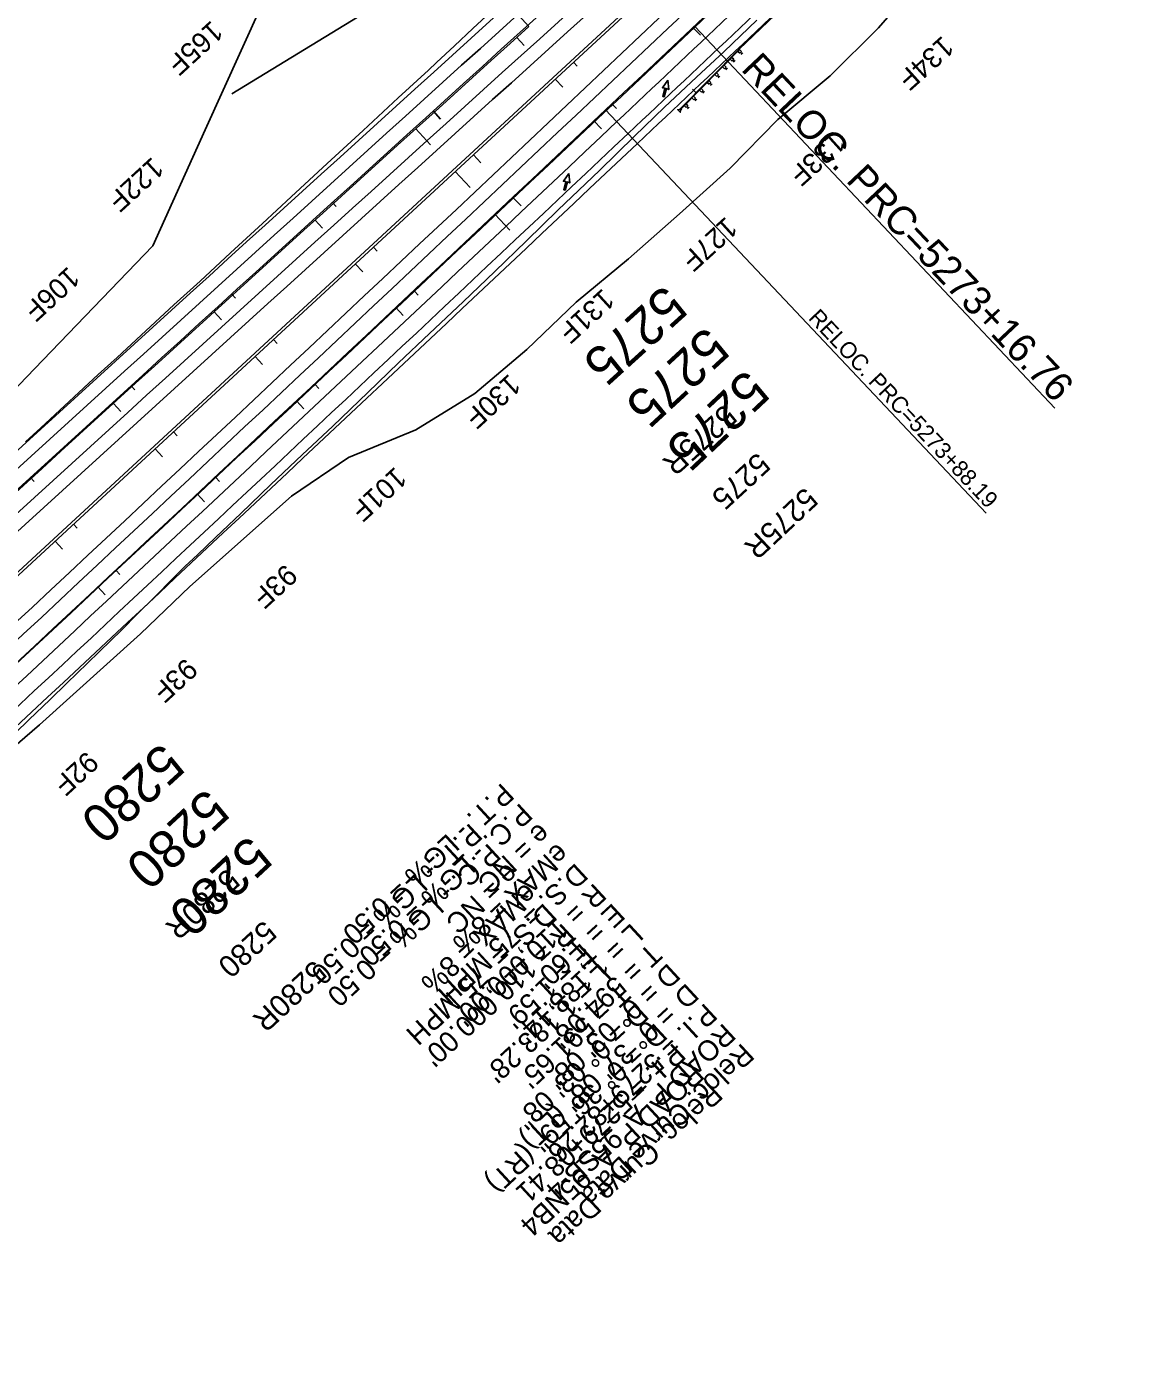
# Model space of a CAD drawing. Extents: x 2160876 to 2175990, y 601436 to 618246.
# Drawn here: x 2164326 to 2165140, y 605855 to 606830 of the extents above; entities that cross this region are included whole.
import ezdxf

# ---------------------------------------------------------------- set-up
doc = ezdxf.new("R2010")
doc.units = 0
for name, color, linetype in [('BNDY-ADJ', 7, 'Continuous'), ('BNDY-ADJ-TXT', 7, 'Continuous'), ('EX-UTIL-ELEC-TXT', 7, 'Continuous'), ('RD_DTM_Major2', 7, 'Continuous'), ('RD_EX_BldgApp_Sign', 7, 'Continuous'), ('RD_EX_BldgApp_Steps', 7, 'Continuous'), ('RD_EX_DV_Prop_Easement Lines', 7, 'Continuous'), ('RD_EX_DV_Prop_Property Lines', 7, 'Continuous'), ('RD_EX_DV_TX_Prop', 7, 'Continuous'), ('RD_EX_Fence_Gate', 7, 'Continuous'), ('RD_EX_RW', 7, 'Continuous'), ('RD_HC_Cl', 7, 'Continuous'), ('RD_HC_Data_Tic', 7, 'Continuous'), ('RD_HC_TX_Sta50', 7, 'Continuous'), ('RD_TX_RoadID', 7, 'Continuous')]:
    doc.layers.add(name, color=color, linetype=linetype)

msp = doc.modelspace()

# ---------------------------------------------------------------- linework, layer by layer
at = {"layer": 'BNDY-ADJ'}
msp.add_line((2172239.89, 613739.88), (2163704.8, 605858.56), dxfattribs=at)
at = {"layer": 'BNDY-ADJ-TXT'}
for centre, start, end in [((2240245.18, 526764.07), 132.7194741, 133.3383414), ((2238442.98, 525213.12), 132.1006067, 132.7194741), ((2089258.03, 686773.08), 312.7194741, 313.3383414)]:
    msp.add_arc(centre, 110000, start, end, dxfattribs=at)
at = {"layer": 'EX-UTIL-ELEC-TXT'}
for centre, radius, start, end in [((2090947.39, 688446.24), 110012, 312.1006067, 312.7194741), ((2240245.18, 526764.07), 110012, 132.7194741, 133.3383414), ((2240245.18, 526764.07), 110000, 132.7194741, 133.3383414), ((2240245.18, 526764.07), 109988, 133.2204237, 133.3383414), ((2240245.18, 526764.07), 109976, 133.2204237, 133.3383414), ((2238442.98, 525213.12), 110012, 132.1006067, 132.7194741), ((2238442.98, 525213.12), 110000, 132.1006067, 132.7194741), ((2238442.98, 525213.12), 109988, 132.1006067, 132.7194741), ((2089258.03, 686773.08), 109988, 312.7194741, 313.3383414), ((2089258.03, 686773.08), 110000, 312.7194741, 313.3383414), ((2089258.03, 686773.08), 110012, 312.8027988, 313.3383414), ((2089258.03, 686773.08), 110024, 312.8637343, 313.3383414)]:
    msp.add_arc(centre, radius, start, end, dxfattribs=at)
at = {"layer": 'RD_DTM_Major2'}
for p, q in [((2164714.67, 606791.06), (2164720.09, 606785.19)), ((2164641.2, 606723.22), (2164652.05, 606711.47)), ((2164567.73, 606655.38), (2164573.16, 606649.51)), ((2164494.26, 606587.54), (2164499.69, 606581.66)), ((2164420.79, 606519.7), (2164426.22, 606513.82)), ((2164347.32, 606451.86), (2164352.75, 606445.98))]:
    msp.add_line(p, q, dxfattribs=at)
at = {"layer": 'RD_EX_BldgApp_Sign'}
for p, q in [((2165000.34, 607057.58), (2163734.9, 605889.07)), ((2164849.65, 606813.07), (2164806.09, 606768.95)), ((2164807.14, 606769.31), (2164850.01, 606812.71)), ((2164848.78, 606811.47), (2164850.01, 606812.71)), ((2164850.2, 606810.06), (2164848.78, 606811.47)), ((2164850.01, 606812.71), (2164849.65, 606813.07)), ((2164850.01, 606812.71), (2164851.43, 606811.31)), ((2164851.43, 606811.31), (2164850.2, 606810.06)), ((2164850.82, 606810.69), (2164851.71, 606809.81)), ((2164837.54, 606800.08), (2164838.76, 606801.33)), ((2164838.76, 606801.33), (2164840.19, 606799.92)), ((2164843.16, 606805.78), (2164844.39, 606807.02)), ((2164844.58, 606804.37), (2164843.16, 606805.78)), ((2164844.39, 606807.02), (2164845.81, 606805.62)), ((2164845.81, 606805.62), (2164844.58, 606804.37)), ((2164845.19, 606804.99), (2164846.08, 606804.12)), ((2164845.47, 606803.49), (2164846.7, 606804.74)), ((2164851.09, 606809.19), (2164852.32, 606810.43)), ((2164831.91, 606794.39), (2164833.14, 606795.64)), ((2164833.34, 606792.99), (2164831.91, 606794.39)), ((2164833.14, 606795.64), (2164834.57, 606794.23)), ((2164834.57, 606794.23), (2164833.34, 606792.99)), ((2164833.95, 606793.61), (2164834.84, 606792.73)), ((2164834.23, 606792.11), (2164835.46, 606793.35)), ((2164838.96, 606798.68), (2164837.54, 606800.08)), ((2164840.19, 606799.92), (2164838.96, 606798.68)), ((2164839.57, 606799.3), (2164840.46, 606798.42)), ((2164839.85, 606797.8), (2164841.08, 606799.05)), ((2164815.36, 606783.68), (2164818.03, 606781.05)), ((2164820.67, 606783.01), (2164821.9, 606784.25)), ((2164822.09, 606781.6), (2164820.67, 606783.01)), ((2164821.9, 606784.25), (2164823.32, 606782.85)), ((2164823.32, 606782.85), (2164822.09, 606781.6)), ((2164822.71, 606782.23), (2164823.6, 606781.35)), ((2164822.98, 606780.72), (2164824.21, 606781.97)), ((2164826.29, 606788.7), (2164827.52, 606789.95)), ((2164827.72, 606787.3), (2164826.29, 606788.7)), ((2164827.52, 606789.95), (2164828.95, 606788.54)), ((2164828.95, 606788.54), (2164827.72, 606787.3)), ((2164828.33, 606787.92), (2164829.22, 606787.04)), ((2164828.61, 606786.42), (2164829.83, 606787.66)), ((2164809.43, 606771.62), (2164810.66, 606772.87)), ((2164810.85, 606770.22), (2164809.43, 606771.62)), ((2164810.66, 606772.87), (2164812.08, 606771.46)), ((2164812.08, 606771.46), (2164810.85, 606770.22)), ((2164815.05, 606777.32), (2164816.28, 606778.56)), ((2164816.47, 606775.91), (2164815.05, 606777.32)), ((2164816.28, 606778.56), (2164817.7, 606777.16)), ((2164817.7, 606777.16), (2164816.47, 606775.91)), ((2164817.09, 606776.53), (2164817.98, 606775.65)), ((2164817.36, 606775.03), (2164818.59, 606776.28)), ((2164806.09, 606768.95), (2164806.8, 606768.25)), ((2164806.58, 606769.09), (2164806.93, 606768.75)), ((2164806.8, 606768.25), (2164807.5, 606768.96)), ((2164807.5, 606768.96), (2164807.15, 606769.31)), ((2164811.47, 606770.84), (2164812.36, 606769.96)), ((2164811.74, 606769.34), (2164812.97, 606770.59))]:
    msp.add_line(p, q, dxfattribs=at)
for points in [[(2165115.33, 607077.64), (2164939.68, 606898.98), (2164849.65, 606813.07)], [(2164806.93, 606768.75), (2164806.43, 606766.81), (2164804.65, 606768.56), (2164806.58, 606769.09)]]:
    msp.add_lwpolyline(points, dxfattribs=at)
at = {"layer": 'RD_EX_BldgApp_Steps'}
for p, q in [((2172672.73, 614139.56), (2163700.62, 605854.69)), ((2164817.42, 606829.42), (2165081.58, 606549.46)), ((2164728.08, 606803.45), (2164730.79, 606800.51)), ((2164756.86, 606772.32), (2164759.6, 606769.41)), ((2164625, 606767.72), (2164630.38, 606761.8)), ((2164654.61, 606735.61), (2164660.04, 606729.73)), ((2164684.04, 606703.78), (2164689.52, 606697.95)), ((2164550.95, 606700.52), (2164553.64, 606697.56)), ((2164581.14, 606667.77), (2164583.86, 606664.83)), ((2164611.16, 606635.31), (2164613.9, 606632.39)), ((2164476.96, 606633.25), (2164479.65, 606630.29)), ((2164507.67, 606599.93), (2164510.39, 606596.99)), ((2164538.22, 606566.9), (2164540.96, 606563.98)), ((2164403.03, 606565.91), (2164405.73, 606562.95)), ((2164434.21, 606532.09), (2164436.92, 606529.15)), ((2164329.16, 606498.5), (2164331.86, 606495.55)), ((2164465.22, 606498.56), (2164467.95, 606495.64)), ((2164360.74, 606464.25), (2164363.45, 606461.31)), ((2164392.15, 606430.29), (2164394.88, 606427.36))]:
    msp.add_line(p, q, dxfattribs=at)
for centre, start, end in [((2240307.46, 526821.59), 132.7194745, 133.3358112), ((2238512.25, 525277.38), 132.0951863, 132.7194745), ((2089327.38, 686837.26), 312.7194745, 313.3358112)]:
    msp.add_arc(centre, 110000, start, end, dxfattribs=at)
at = {"layer": 'RD_EX_DV_Prop_Easement Lines'}
for points in [[(2164797.37, 606790.4), (2164793.35, 606784.69), (2164794.91, 606784.5)], [(2164794.91, 606784.5), (2164795.21, 606784.46), (2164793.6, 606778.44), (2164794.13, 606778.3)], [(2164794.13, 606778.3), (2164794.65, 606778.16), (2164796.27, 606784.18), (2164797.99, 606783.44), (2164797.37, 606790.4)], [(2164724.61, 606721.8), (2164720.59, 606716.09), (2164722.15, 606715.9)], [(2164722.15, 606715.9), (2164722.45, 606715.86), (2164720.84, 606709.84), (2164721.37, 606709.7)], [(2164721.37, 606709.7), (2164721.89, 606709.56), (2164723.51, 606715.58), (2164725.23, 606714.85), (2164724.61, 606721.8)]]:
    msp.add_lwpolyline(points, dxfattribs=at)
at = {"layer": 'RD_EX_DV_Prop_Property Lines'}
msp.add_lwpolyline([(2164730.74, 606938.91), (2164716.18, 606926.46), (2164476.92, 606780.31)], dxfattribs=at)
at = {"layer": 'RD_EX_Fence_Gate'}
msp.add_line((2164916.68, 606793.4), (2164878.07, 606761.51), dxfattribs=at)
for points in [[(2164225.61, 606467.59), (2164332.12, 606578.34), (2164418.96, 606668.62), (2164457.45, 606753.78), (2164511.45, 606873.27), (2164543.88, 606914.28), (2164546.6, 606930.7)], [(2164985, 606866.81), (2164952.16, 606828.67), (2164916.68, 606793.4)], [(2164878.07, 606761.51), (2164843.19, 606725.58), (2164805.99, 606692.16), (2164768.42, 606659.15), (2164729.87, 606627.2), (2164693.78, 606592.58), (2164655.63, 606560.2), (2164612.21, 606533.51), (2164562.76, 606513.36), (2164520.99, 606484.89), (2164446.22, 606418.46), (2164410.07, 606383.91), (2164335.76, 606316.98), (2164259.94, 606251.69), (2164185.81, 606184.56), (2164112.55, 606116.5), (2164041.34, 606046.21), (2163998.32, 605983.1)]]:
    msp.add_lwpolyline(points, dxfattribs=at)
at = {"layer": 'RD_EX_RW'}
msp.add_line((2164878.07, 606761.51), (2164916.68, 606793.4), dxfattribs=at)
for points in [[(2164546.43, 606929.66), (2164543.88, 606914.28), (2164511.45, 606873.27), (2164457.45, 606753.78), (2164418.96, 606668.62), (2164332.12, 606578.34), (2164225.61, 606467.59)], [(2164916.68, 606793.4), (2164952.16, 606828.67), (2164985, 606866.81)], [(2164325.38, 606524.67), (2164336.78, 606535.15), (2164357.61, 606554.39), (2164378.89, 606574.09), (2164392.77, 606586.75), (2164410.35, 606602.99), (2164434.52, 606625.3), (2164453.74, 606642.72), (2164476.15, 606663.45), (2164499.56, 606685.09), (2164520.61, 606704.6), (2164547.13, 606729.15), (2164573.45, 606753.37), (2164599.18, 606777.36), (2164621.44, 606797.59), (2164627.44, 606803.24), (2164640.52, 606815.51), (2164654.08, 606828.15), (2164670.32, 606843.07)], [(2164862.78, 606834.47), (2164838.63, 606811.46), (2164818.42, 606792.51), (2164794.83, 606770.59), (2164772.91, 606749.22), (2164747.16, 606724.05), (2164726.84, 606704.72), (2164716.78, 606695.01), (2164693.55, 606672.34), (2164670.33, 606649.84), (2164646.91, 606627.52), (2164622.24, 606604.39), (2164599.54, 606582.65), (2164576.94, 606560.87), (2164551.34, 606536.37), (2164528.78, 606515.18), (2164505.8, 606493.41), (2164483.7, 606472.22), (2164465.29, 606454.77), (2164451.8, 606441.8), (2164442.88, 606433.39), (2164434.66, 606425.29), (2164419.29, 606409.76), (2164408.31, 606398.92), (2164395.86, 606386.28), (2164388.19, 606378.82), (2164371, 606362.18), (2164355.85, 606347.49), (2164343.59, 606335.52), (2164327.97, 606320.63), (2164318.05, 606311.05)], [(2164185.82, 606184.57), (2164259.94, 606251.69), (2164335.76, 606316.98), (2164410.07, 606383.91), (2164446.22, 606418.46), (2164520.99, 606484.89), (2164562.76, 606513.36), (2164612.21, 606533.51), (2164655.63, 606560.2), (2164693.78, 606592.58), (2164729.87, 606627.2), (2164768.42, 606659.15), (2164805.99, 606692.16), (2164843.19, 606725.58), (2164878.07, 606761.51)]]:
    msp.add_lwpolyline(points, dxfattribs=at)
at = {"layer": 'RD_HC_Cl'}
for p, q in [((2164686.42, 606821.76), (2164691.79, 606815.82)), ((2164815.77, 606829.07), (2164821.26, 606823.25)), ((2164612.26, 606754.67), (2164623, 606742.81)), ((2164743.01, 606760.47), (2164748.5, 606754.65)), ((2164538.16, 606687.52), (2164543.54, 606681.59)), ((2164670.24, 606691.88), (2164681.21, 606680.23)), ((2164464.13, 606620.3), (2164469.51, 606614.38)), ((2164597.41, 606623.36), (2164602.89, 606617.53)), ((2164390.15, 606553.01), (2164395.54, 606547.1)), ((2164524.52, 606554.9), (2164529.99, 606549.06)), ((2164451.56, 606486.51), (2164457.03, 606480.67)), ((2164378.54, 606418.18), (2164384.01, 606412.34))]:
    msp.add_line(p, q, dxfattribs=at)
at = {"layer": 'RD_HC_TX_Sta50'}
for p, q in [((2164695.19, 606829.68), (2164538.86, 607002.68)), ((2164751.61, 606768.58), (2165031.11, 606472.37))]:
    msp.add_line(p, q, dxfattribs=at)
at = {"layer": 'RD_TX_RoadID'}
for centre, radius, start, end in [((2090947.39, 688446.24), 110022, 312.1006067, 312.7194741), ((2240245.18, 526764.07), 110022, 132.7194741, 133.3383414), ((2240245.18, 526764.07), 109966, 133.2204237, 133.3383414), ((2238442.98, 525213.12), 110022, 132.1006067, 132.7194741), ((2238442.98, 525213.12), 109978, 132.1006067, 132.7194741), ((2089258.03, 686773.08), 109978, 312.7194741, 313.3383414), ((2089258.03, 686773.08), 110034, 312.8031209, 313.3383414)]:
    msp.add_arc(centre, radius, start, end, dxfattribs=at)

# ---------------------------------------------------------------- texts
at = {"layer": 'RD_EX_BldgApp_Steps'}
for s, height, rotation, p in [('RELOC. PRC=5273+16.76', 21, 313.33581, (2164850.37, 606797.95)), ('5275', 28, 222.19858, (2164794.93, 606641.03)), ('5275', 28, 222.71947, (2164825.64, 606610.43)), ('5275', 28, 223.24037, (2164854.92, 606578.96)), ('5280', 28, 222.45901, (2164425.57, 606304.85)), ('5280', 28, 222.71947, (2164458.39, 606271.31)), ('P.T. - LG% = 0.50', 15, 222.79202, (2164652.15, 606245.43)), ('5280', 28, 222.97993, (2164489.71, 606236.83)), ('P.C. - LG% = 0.50', 15, 222.79202, (2164665.74, 606230.75)), ('e = NC', 15, 222.79202, (2164679.32, 606216.08)), ('eMAX = 8%', 15, 222.79202, (2164692.91, 606201.4)), ('D.S. =  75 MPH', 15, 222.79202, (2164706.5, 606186.72)), ("R = 110,000.00'", 15, 222.79202, (2164720.08, 606172.05)), ("E = 1.59'", 15, 222.79202, (2164733.67, 606157.37)), ("L = 1,183.28'", 15, 222.79202, (2164747.26, 606142.69)), ("T = 591.65'", 15, 222.79202, (2164760.84, 606128.02)), ('D = 0° 03\' 08"', 15, 222.79202, (2164774.43, 606113.34)), ('D', 15, 222.79202, (2164788.02, 606098.67)), ('    = 0° 36\' 59" (RT)', 15, 222.79202, (2164788.02, 606098.67)), ('P.I. = 5279+08.41', 15, 222.79202, (2164801.6, 606083.99)), ('ROAD P_A_95NB4', 15, 222.79202, (2164815.19, 606069.31)), ('Reloc. Curve Data', 15, 222.79202, (2164828.78, 606054.64))]:
    msp.add_text(s, height=height, rotation=rotation, dxfattribs=at).set_placement(p)
at = {"layer": 'RD_EX_DV_TX_Prop'}
for s, p in [('5275', (2164863.19, 606517.72)), ('5280', (2164500.56, 606174.13))]:
    msp.add_text(s, height=16, rotation=222.71947, dxfattribs=at).set_placement(p)
at = {"layer": 'RD_EX_Fence_Gate'}
for s, rotation, p in [('165F', 222.52345, (2164462.07, 606834.82)), ('134F', 221.92831, (2164999.05, 606823.59)), ('133F', 222.1193, (2164919.32, 606753.42)), ('122F', 222.52345, (2164418.53, 606734.57)), ('127F', 222.31028, (2164839.99, 606690.78)), ('106F', 222.52345, (2164356.83, 606654.13)), ('131F', 222.50127, (2164749.53, 606638.02)), ('130F', 222.52345, (2164680.67, 606575.32)), ('101F', 222.52345, (2164597.01, 606507.13)), ('93F', 222.52345, (2164516.52, 606435.79)), ('93F', 222.52345, (2164443.18, 606366.74)), ('92F', 222.52345, (2164370.47, 606298.39))]:
    msp.add_text(s, height=15, rotation=rotation, dxfattribs=at).set_placement(p)
at = {"layer": 'RD_HC_Data_Tic'}
for s, rotation, p in [('5275R', 222.15885, (2164838.87, 606553.03)), ('5275R', 223.2801, (2164898, 606492.11)), ('5280R', 222.41928, (2164473.6, 606212.3)), ('5280R', 223.01967, (2164537.3, 606144.99))]:
    msp.add_text(s, height=16, rotation=rotation, dxfattribs=at).set_placement(p)
at = {"layer": 'RD_HC_TX_Sta50'}
for s, height, rotation, p in [('RELOC. PRC=5273+88.19', 12, 313.33834, (2164899.89, 606615.2)), ('P.T. - LG% = 0.50', 15, 222.71947, (2164675.51, 606274.9)), ('P.C. - LG% = 0.50', 15, 222.71947, (2164689.08, 606260.21)), ('e = NC', 15, 222.71947, (2164702.65, 606245.52)), ('eMAX = 8%', 15, 222.71947, (2164716.21, 606230.82)), ('D.S. =  75 MPH', 15, 222.71947, (2164729.78, 606216.13)), ("R = 110,000.00'", 15, 222.71947, (2164743.35, 606201.43)), ("E = 1.60'", 15, 222.71947, (2164756.92, 606186.74)), ("L = 1,188.14'", 15, 222.71947, (2164770.49, 606172.05)), ("T = 594.08'", 15, 222.71947, (2164784.06, 606157.35)), ('D = 0° 03\' 08"', 15, 222.71947, (2164797.62, 606142.66)), ('D', 15, 222.71947, (2164811.19, 606127.97)), ('    = 0° 37\' 08" (LT)', 15, 222.71947, (2164811.19, 606127.97)), ('P.I. = 5279+82.26', 15, 222.71947, (2164824.76, 606113.27)), ('ROAD P_A_95SB-4', 15, 222.71947, (2164838.33, 606098.58)), ('Reloc. Curve Data', 15, 222.71947, (2164851.9, 606083.88))]:
    msp.add_text(s, height=height, rotation=rotation, dxfattribs=at).set_placement(p)

doc.saveas('drawing.dxf')
